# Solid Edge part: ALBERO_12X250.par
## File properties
Subject: ALBERO_12X250
Author: f_grande
Template: Normal.par
Last saved by: f_grande
Revision: 3
Application: Solid Edge
Material: Acciaio
Stile della faccia: Acciaio
Stile di riempimento: ANSI32(Acciaio)
Stile virtuale: Acciaio lavorato a macchina
Coef. of Thermal Exp: 0.0
Thermal Conductivity: 32.0
Specific Heat: 481.0
Modulus of Elasticity: 199947953000.0
Poisson's Ratio: 0.29
Yield Stress: 262000766.0
Ultimate Stress: 358527364.0
Elongation: 0.0
Tipo di contenuto documento: 0
Densità: 7833,000 kg/m^3
Precisione: 0,990
Document Number: KRO103
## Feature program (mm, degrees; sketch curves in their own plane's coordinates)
sketch for "unnamed Protrusion 1" plane through (0, 0, 0) normal (0, -1, 0) x-axis (1, 0, 0)
  circle centre (0, 0) radius 6
extrude "unnamed Protrusion 1" add finite 250 along -normal
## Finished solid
Body 1: solid body, 3 faces, 2 edges, 0 vertices.
  Faces by surface: plane 2, cylinder 1
  Edges by curve: circle 2
Bounding box of the edges (mm): 12.000 x 250.000 x 12.000, from (-6, 0, -6) to (6, 250, 6).
Cylindrical faces by radius (mm): R6 x1
Planar faces by outward normal: +y 1, -y 1
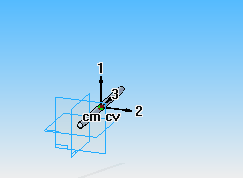
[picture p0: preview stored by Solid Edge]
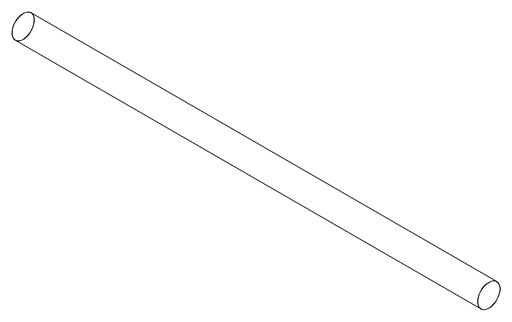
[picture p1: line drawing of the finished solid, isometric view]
